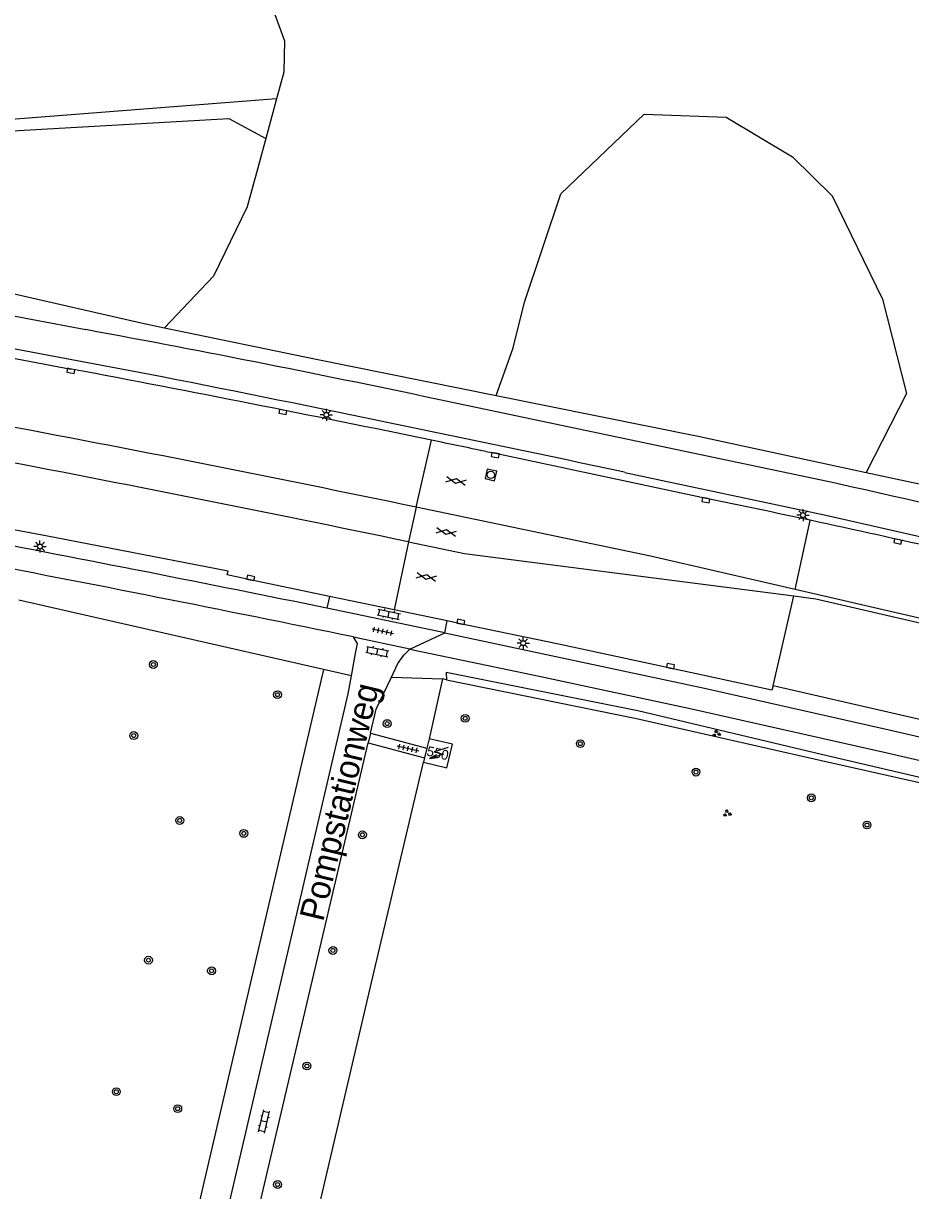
# Model space of a CAD drawing. Extents: x 128999 to 131010, y 395498 to 399007.
# Drawn here: x 129211.4 to 129301.8, y 396978.2 to 397097.3 of the extents above; entities that cross this region are included whole.
import ezdxf

# ---------------------------------------------------------------- set-up
doc = ezdxf.new("R2010")
doc.units = 0
for name, color, linetype in [('gg-afsc-hekwerk', 7, 'Continuous'), ('gg-anno-huisnummerreeks BGT', 7, 'Continuous'), ('gg-anno-openbare ruimte label', 7, 'Continuous'), ('gg-bbg-hoofdgebouw', 7, 'Continuous'), ('gg-knt-BGT kruinlijn', 7, 'Continuous'), ('gg-knt-bovenkant onderkant talud', 7, 'Continuous'), ('gg-knt-onverhard', 7, 'Continuous'), ('gg-knt-verharding', 7, 'Continuous'), ('gg-knt-verharding nz', 7, 'Continuous'), ('gt-grn-groengrens', 7, 'Continuous'), ('gt-grn-weggrens', 7, 'Continuous'), ('gt-symb-boom', 7, 'Continuous'), ('gt-symb-gesloten verharding', 7, 'Continuous'), ('gt-symb-groenvak', 7, 'Continuous'), ('gt-symb-klinker verharding', 7, 'Continuous'), ('gt-symb-kolk', 7, 'Continuous'), ('gt-symb-lichtmast', 7, 'Continuous'), ('gt-symb-rioolschacht', 7, 'Continuous'), ('gt-symb-tegel verharding', 7, 'Continuous'), ('gt-symb-trafo symbool', 7, 'Continuous')]:
    doc.layers.add(name, color=color, linetype=linetype)

# ---------------------------------------------------------------- blocks, each defined once
blk = doc.blocks.new('gt0-GESVH1')
at = {"layer": 'gt-symb-gesloten verharding'}
for p, q in [((-0.99, -0.26), (0.01, 0.24)), ((0.01, -0.26), (-0.99, 0.24)), ((0.01, 0.24), (1.01, -0.26)), ((1.01, 0.24), (0.01, -0.26))]:
    blk.add_line(p, q, dxfattribs=at)
blk = doc.blocks.new('gt0-KOLK')
at = {"layer": 'gt-symb-kolk'}
blk.add_lwpolyline([(0, 0), (0.38, 0), (0.38, 0.4), (-0.38, 0.4), (-0.38, 0), (0, 0)], dxfattribs=at)
blk = doc.blocks.new('gt0-LMAST')
at = {"layer": 'gt-symb-lichtmast'}
for p, q in [((-0.18, 0.17), (-0.45, 0.44)), ((-0.01, 0.25), (-0.01, 0.62)), ((0.17, 0.17), (0.44, 0.44)), ((-0.26, 0), (-0.63, 0)), ((-0.18, -0.18), (-0.45, -0.45)), ((-0.01, -0.25), (-0.01, -0.63)), ((0.44, -0.45), (0.17, -0.18)), ((0.24, 0), (0.62, 0))]:
    blk.add_line(p, q, dxfattribs=at)
blk.add_circle((-0.01, 0), 0.25, dxfattribs=at)
blk = doc.blocks.new('gt0-BOOM')
at = {"layer": 'gt-symb-boom'}
for radius in [0.4, 0.2]:
    blk.add_circle((0, 0), radius, dxfattribs=at)
blk = doc.blocks.new('gt0-KL1')
at = {"layer": 'gt-symb-klinker verharding'}
for p, q in [((-1.15, 0.3), (1.15, 0.3)), ((-1, -0.3), (-1, 0.3)), ((-0.5, 0.3), (-0.5, 0.45)), ((0, -0.3), (0, 0.3)), ((0.5, 0.3), (0.5, 0.45)), ((1, -0.3), (1, 0.3)), ((-1.15, -0.3), (1.15, -0.3)), ((-0.5, -0.45), (-0.5, -0.3)), ((0.5, -0.45), (0.5, -0.3))]:
    blk.add_line(p, q, dxfattribs=at)
blk = doc.blocks.new('gt0-TEG1')
at = {"layer": 'gt-symb-tegel verharding'}
for p, q in [((-1.12, 0), (1.12, 0)), ((-0.9, -0.25), (-0.9, 0.25)), ((-0.45, -0.25), (-0.45, 0.25)), ((0, -0.25), (0, 0.25)), ((0.45, -0.25), (0.45, 0.25)), ((0.9, -0.25), (0.9, 0.25))]:
    blk.add_line(p, q, dxfattribs=at)
blk = doc.blocks.new('gt0-HSP')
at = {"layer": 'gt-symb-trafo symbool'}
for points in [[(0.77, 0.75), (-0.53, 0), (0.47, 0), (-0.83, -0.75)], [(-0.22, -0.24), (-0.83, -0.75), (-0.08, -0.48)]]:
    blk.add_lwpolyline(points, dxfattribs=at)
blk = doc.blocks.new('gt0-GRVAK')
at = {"layer": 'gt-symb-groenvak'}
for p, q in [((-0.11, 0.19), (-0.23, 0.24)), ((-0.18, 0.15), (0.09, 0.15)), ((-0.09, 0.21), (-0.16, 0.32)), ((-0.05, 0.21), (-0.05, 0.39)), ((0, 0.21), (0.06, 0.32)), ((0.01, 0.19), (0.13, 0.24)), ((0.26, -0.05), (0.2, 0.06)), ((0.31, -0.05), (0.31, 0.13)), ((0.35, -0.05), (0.41, 0.06)), ((-0.24, -0.23), (-0.36, -0.18)), ((-0.32, -0.26), (-0.05, -0.26)), ((-0.23, -0.21), (-0.29, -0.1)), ((-0.18, -0.2), (-0.18, -0.02)), ((-0.14, -0.21), (-0.07, -0.1)), ((-0.12, -0.23), (0, -0.18)), ((0.24, -0.07), (0.12, -0.02)), ((0.17, -0.11), (0.44, -0.11)), ((0.37, -0.07), (0.49, -0.02))]:
    blk.add_line(p, q, dxfattribs=at)
blk = doc.blocks.new('gt0-RS')
at = {"layer": 'gt-symb-rioolschacht'}
blk.add_lwpolyline([(-0.5, -0.5), (0.5, -0.5), (0.5, 0.5), (-0.5, 0.5)], close=True, dxfattribs=at)
blk.add_circle((0, 0), 0.375, dxfattribs=at)

msp = doc.modelspace()

# ---------------------------------------------------------------- linework, layer by layer
at = {"layer": 'gg-afsc-hekwerk'}
msp.add_line((129223.38, 397066.69), (129225.76, 397066.19), dxfattribs=at)
for points in [[(129096.44, 397095.78), (129150.23, 397083.43), (129223.38, 397066.69)], [(129225.76, 397066.19), (129241.22, 397062.98), (129259.57, 397059.28)], [(129259.57, 397059.28), (129280.16, 397055.13), (129297.3, 397051.44)], [(129297.3, 397051.44), (129306.99, 397049.35), (129321.75, 397046.03)]]:
    msp.add_lwpolyline(points, dxfattribs=at)
at = {"layer": 'gg-bbg-hoofdgebouw'}
for p, q in [((129252.73, 397024.27), (129252.5, 397023.3)), ((129252.27, 397022.33), (129252.16, 397021.87)), ((129252.5, 397023.3), (129252.27, 397022.33))]:
    msp.add_line(p, q, dxfattribs=at)
msp.add_lwpolyline([(129252.16, 397021.87), (129254.55, 397021.31), (129255.12, 397023.72), (129252.73, 397024.27)], dxfattribs=at)
at = {"layer": 'gg-knt-BGT kruinlijn'}
msp.add_lwpolyline([(129378.84, 397002.49), (129373.72, 397004.36), (129341.73, 397011.78), (129319.05, 397016.5), (129292.75, 397022.66), (129274.01, 397027.12), (129254.48, 397031.03), (129254.52, 397030.3)], dxfattribs=at)
at = {"layer": 'gg-knt-bovenkant onderkant talud'}
msp.add_lwpolyline([(129254.52, 397030.3), (129273.87, 397026.34), (129292.73, 397022.04), (129341.64, 397011.07), (129354.23, 397008.45)], dxfattribs=at)
at = {"layer": 'gg-knt-onverhard'}
for points in [[(129142.13, 397094.08), (129145.61, 397091.22), (129149.87, 397088.04), (129157.65, 397085.12), (129170.74, 397082.8), (129174.93, 397082.6), (129179.28, 397082.98), (129201.29, 397085.76), (129232.33, 397087.53), (129236.1, 397085.5)], [(129237.19, 397089.55), (129200.09, 397086.67), (129179.24, 397084), (129169.15, 397084.15), (129157.97, 397086.09), (129151.17, 397088.74), (129148.1, 397091.13), (129143.97, 397094.29)]]:
    msp.add_lwpolyline(points, dxfattribs=at)
at = {"layer": 'gg-knt-verharding'}
for p, q in [((129217.73, 397066), (129191.26, 397070.96)), ((129225.53, 397061.18), (129191.54, 397067.57)), ((129294, 397050.37), (129254.44, 397058.72)), ((129251.42, 397047.89), (129250.62, 397044.36)), ((129242.59, 397038.8), (129242.32, 397037.6)), ((129249.18, 397037.43), (129242.59, 397038.8)), ((129254.33, 397035.09), (129242.32, 397037.6)), ((129254.59, 397036.3), (129249.18, 397037.43)), ((129254.33, 397035.09), (129254.59, 397036.3)), ((129250.76, 397033.42), (129245.04, 397034.65)), ((129244.5, 397028.87), (129244.82, 397030.68)), ((129247.33, 397027.28), (129248.89, 397030.57)), ((129207.73, 396871.48), (129244.5, 397028.87)), ((129246.76, 397024.85), (129247.33, 397027.28)), ((129246.76, 397024.85), (129246.53, 397023.87)), ((129246.76, 397024.85), (129252.5, 397023.3)), ((129221.6, 396917.68), (129246.53, 397023.87)), ((129246.53, 397023.87), (129252.27, 397022.33))]:
    msp.add_line(p, q, dxfattribs=at)
for points in [[(129149.94, 397074.56), (129173.06, 397070.06), (129194.59, 397066.08), (129216.26, 397061.99)], [(129258.53, 397053.58), (129259.52, 397053.4), (129280.99, 397048.8)], [(129272.67, 397051.45), (129293.16, 397047.09), (129309.5, 397043.37), (129325.26, 397039.65), (129340.58, 397035.96)], [(129290.05, 397039.49), (129275.31, 397042.91), (129251.42, 397047.89)], [(129242.59, 397038.8), (129234.51, 397040.48), (129232.16, 397041.01), (129232.26, 397041.38), (129213.65, 397044.98), (129205.83, 397046.45)], [(129250.62, 397044.36), (129256.35, 397043.18), (129289.93, 397038.84)], [(129373.49, 397019.76), (129373.61, 397020.17), (129290.05, 397039.49)], [(129289.93, 397038.84), (129292.15, 397038.55), (129373.49, 397019.76)], [(129287.81, 397029.66), (129287.68, 397029.24), (129277.3, 397031.49), (129265.62, 397033.98), (129255.93, 397036), (129254.59, 397036.3)], [(129244.82, 397030.68), (129245.23, 397032.97), (129245.44, 397033.99), (129245.04, 397034.65)], [(129254.33, 397035.09), (129280.82, 397029.43), (129299.63, 397025.19), (129330.54, 397018.06), (129350.35, 397013.47)], [(129248.89, 397030.57), (129249.54, 397031.96), (129250.17, 397032.81), (129250.76, 397033.42)], [(129250.76, 397033.42), (129263.97, 397030.67), (129279.36, 397027.36), (129299.12, 397022.9), (129330.46, 397015.68), (129354.56, 397010.09)], [(129350.76, 397015.11), (129321.5, 397021.84), (129302.46, 397026.3), (129287.81, 397029.66)]]:
    msp.add_lwpolyline(points, dxfattribs=at)
for centre, radius, start, end in [((128966.38, 395703.19), 1385.8, 78.00236, 79.55007), ((128818.66, 394954.6), 2144.57, 78.31582, 79.3154), ((128585.43, 393842.85), 3281.38, 77.91079, 78.75123), ((128824.36, 395005.28), 2086.78, 78.19113, 79.40806), ((128840.57, 395059.36), 2037.54, 78.16299, 78.32266), ((128739.91, 394594.87), 2502.17, 78.22293, 79.23642), ((129017.3, 395802.62), 1278.06, 76.0038, 77.49643), ((128980.7, 395604.7), 1474.99, 77.83278, 78.25295), ((128975.44, 395578.99), 1501.23, 76.7721, 77.84354), ((128692.55, 394347.87), 2745.33, 78.44814, 79.2314), ((128691.49, 394350.12), 2741.01, 78.34907, 79.20183)]:
    msp.add_arc(centre, radius, start, end, dxfattribs=at)
at = {"layer": 'gg-knt-verharding nz'}
for p, q in [((129290.05, 397039.49), (129291.57, 397046.55)), ((129287.81, 397029.66), (129289.93, 397038.84))]:
    msp.add_line(p, q, dxfattribs=at)
at = {"layer": 'gt-grn-groengrens'}
for p, q in [((129237.19, 397089.55), (129236.1, 397085.5)), ((129241.97, 397031.34), (129210.91, 397038.42)), ((129241.97, 397031.34), (129204.01, 396868.46)), ((129244.82, 397030.68), (129241.97, 397031.34)), ((129248.89, 397030.57), (129254.1, 397030.39)), ((129254.1, 397030.39), (129252.73, 397024.27)), ((129254.52, 397030.3), (129254.1, 397030.39))]:
    msp.add_line(p, q, dxfattribs=at)
for points in [[(129236.91, 397123.97), (129234.55, 397119.64), (129233.69, 397114.28), (129233.86, 397109.1), (129235.41, 397102.54), (129238, 397095.46), (129237.93, 397092.26), (129237.19, 397089.55)], [(129259.57, 397059.28), (129261.3, 397064.14), (129262.45, 397068.8), (129266.17, 397079.86), (129274.67, 397088), (129283.01, 397087.68), (129289.77, 397083.64), (129293.81, 397079.66), (129298.95, 397069.11), (129301.41, 397059.48), (129297.3, 397051.44)], [(129236.1, 397085.5), (129235.24, 397082.36), (129234.2, 397078.54), (129230.75, 397071.46), (129225.76, 397066.19)], [(129227.55, 396916.8), (129246.99, 397000), (129252.16, 397021.87)]]:
    msp.add_lwpolyline(points, dxfattribs=at)
at = {"layer": 'gt-grn-weggrens'}
for p, q in [((129251.42, 397047.89), (129252.97, 397054.74)), ((129250.62, 397044.36), (129249.18, 397037.43)), ((129250.76, 397033.42), (129254.33, 397035.09))]:
    msp.add_line(p, q, dxfattribs=at)

# ---------------------------------------------------------------- block references
at = {"layer": 'gt-symb-boom'}
for p in [(129224.63, 397031.85), (129237.28, 397028.77), (129248.46, 397025.82), (129256.41, 397026.36), (129222.63, 397024.6), (129268.15, 397023.77), (129279.94, 397020.87), (129291.7, 397018.25), (129227.32, 397015.94), (129297.37, 397015.48), (129233.85, 397014.62), (129245.94, 397014.48), (129224.13, 397001.69), (129242.93, 397002.68), (129230.56, 397000.6), (129240.28, 396990.89), (129220.85, 396988.27), (129227.11, 396986.54), (129237.29, 396978.8)]:
    msp.add_blockref('gt0-BOOM', p, dxfattribs=at)
at = {"layer": 'gt-symb-gesloten verharding'}
for p, rotation in [((129255.46, 397050.58), -9.905079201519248), ((129254.47, 397045.37), -9.90507919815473), ((129252.44, 397040.79), -9.905079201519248)]:
    msp.add_blockref('gt0-GESVH1', p, dxfattribs=dict(at, rotation=rotation))
at = {"layer": 'gt-symb-groenvak', "rotation": -7.068140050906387}
for p in [(129282.03, 397024.79), (129283.11, 397016.66)]:
    msp.add_blockref('gt0-GRVAK', p, dxfattribs=at)
at = {"layer": 'gt-symb-klinker verharding'}
for p, rotation in [((129248.62, 397036.97), -11.53462065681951), ((129247.46, 397033.17), -11.53462065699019), ((129235.91, 396985.22), 76.82507339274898)]:
    msp.add_blockref('gt0-KL1', p, dxfattribs=dict(at, rotation=rotation))
at = {"layer": 'gt-symb-kolk'}
for p, rotation in [((129216.26, 397061.99), 169.3183792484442), ((129237.87, 397057.8), 168.72646790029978), ((129259.52, 397053.4), 169.76155744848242), ((129280.99, 397048.8), 167.90186104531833), ((129300.55, 397044.59), 167.48869921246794), ((129234.51, 397040.48), -11.841693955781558), ((129255.93, 397036), -11.743599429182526), ((129277.3, 397031.49), -12.204092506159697)]:
    msp.add_blockref('gt0-KOLK', p, dxfattribs=dict(at, rotation=rotation))
at = {"layer": 'gt-symb-lichtmast'}
for p in [(129242.27, 397057.32), (129290.86, 397047.09), (129213.08, 397043.89), (129262.34, 397034.03)]:
    msp.add_blockref('gt0-LMAST', p, dxfattribs=at)
at = {"layer": 'gt-symb-rioolschacht', "rotation": 77.88608007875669}
msp.add_blockref('gt0-RS', (129259.03, 397051.19), dxfattribs=at)
at = {"layer": 'gt-symb-tegel verharding'}
for p, rotation in [((129248.01, 397035.24), -12.118760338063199), ((129250.58, 397023.29), -12.882979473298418)]:
    msp.add_blockref('gt0-TEG1', p, dxfattribs=dict(at, rotation=rotation))
at = {"layer": 'gt-symb-trafo symbool', "rotation": -13.007504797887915}
msp.add_blockref('gt0-HSP', (129253.76, 397022.81), dxfattribs=at)

# ---------------------------------------------------------------- texts
at = {"layer": 'gg-anno-huisnummerreeks BGT'}
msp.add_text('550', height=1, rotation=347, dxfattribs=at).set_placement((129252.42, 397022.57))
at = {"layer": 'gg-anno-openbare ruimte label'}
msp.add_text('Pompstationweg', height=2.5, rotation=76.6, dxfattribs=at).set_placement((129241.93, 397005.54))

doc.saveas('drawing.dxf')
